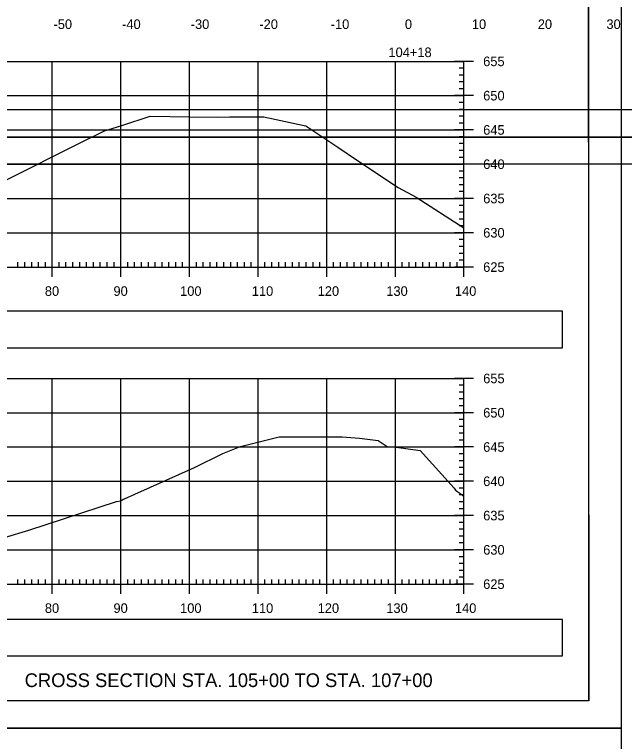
# Model space of a CAD drawing. Extents: x 1381471 to 1382703, y 370300 to 371487.
# Drawn here: x 1382079.3 to 1382168.2, y 370972.4 to 371078.4 of the extents above; entities that cross this region are included whole.
import ezdxf

# ---------------------------------------------------------------- set-up
doc = ezdxf.new("R2010")
doc.units = 0
for name, color, linetype in [('Level 15', 7, 'Continuous'), ('Level 18', 7, 'Continuous'), ('Level 22', 7, 'Continuous'), ('Level 26', 7, 'Continuous'), ('Level 4', 7, 'Continuous'), ('Level 45', 7, 'Continuous'), ('Level 5', 7, 'Continuous'), ('Level 6', 7, 'Continuous')]:
    doc.layers.add(name, color=color, linetype=linetype)

msp = doc.modelspace()

# ---------------------------------------------------------------- linework, layer by layer
at = {"layer": 'Level 18'}
for points in [[(1382078.02, 371054.19), (1382088.62, 371059.56), (1382092.36, 371061.41), (1382094.91, 371062.2), (1382099.03, 371063.56), (1382104.81, 371063.46), (1382108.85, 371063.42), (1382110.67, 371063.45), (1382115.58, 371063.45), (1382120.55, 371062.4), (1382121.71, 371062.14), (1382126.39, 371059.03), (1382129.23, 371057.09), (1382135.18, 371053.13), (1382137.81, 371051.74), (1382144.77, 371047.25)], [(1382077.82, 371002.09), (1382081.37, 371003.19), (1382094.14, 371007.36), (1382094.77, 371007.46), (1382095.09, 371007.68), (1382095.3, 371007.72), (1382096.81, 371008.41), (1382105.51, 371012.33), (1382109.63, 371014.35), (1382112.04, 371015.3), (1382112.15, 371015.34), (1382112.22, 371015.36), (1382117.82, 371016.76), (1382124.52, 371016.79), (1382127.01, 371016.79), (1382129.55, 371016.57), (1382132.27, 371016.23), (1382133.6, 371015.39), (1382134.89, 371015.28), (1382138.39, 371014.79), (1382143.35, 371009.28), (1382143.54, 371009.02), (1382143.7, 371008.93), (1382144.77, 371008.15)]]:
    msp.add_lwpolyline(points, dxfattribs=at)
at = {"layer": 'Level 22'}
for p, q in [((1381864.77, 371071.54), (1382144.77, 371071.54)), ((1382084.77, 371041.54), (1382084.77, 371071.54)), ((1382094.77, 371041.54), (1382094.77, 371071.54)), ((1382104.77, 371041.54), (1382104.77, 371071.54)), ((1382114.77, 371041.54), (1382114.77, 371071.54)), ((1382124.77, 371041.54), (1382124.77, 371071.54)), ((1382134.77, 371041.54), (1382134.77, 371071.54)), ((1382144.77, 371041.54), (1382144.77, 371071.54)), ((1381864.77, 371066.54), (1382144.77, 371066.54)), ((1381864.77, 371061.54), (1382144.77, 371061.54)), ((1381864.77, 371056.54), (1382144.77, 371056.54)), ((1381864.77, 371051.54), (1382144.77, 371051.54)), ((1381864.77, 371046.54), (1382144.77, 371046.54)), ((1381864.77, 371041.54), (1382144.77, 371041.54)), ((1381864.77, 371025.3), (1382144.77, 371025.3)), ((1382084.77, 370995.3), (1382084.77, 371025.3)), ((1382094.77, 370995.3), (1382094.77, 371025.3)), ((1382104.77, 370995.3), (1382104.77, 371025.3)), ((1382114.77, 370995.3), (1382114.77, 371025.3)), ((1382124.77, 370995.3), (1382124.77, 371025.3)), ((1382134.77, 370995.3), (1382134.77, 371025.3)), ((1382144.77, 370995.3), (1382144.77, 371025.3)), ((1381864.77, 371020.3), (1382144.77, 371020.3)), ((1381864.77, 371015.3), (1382144.77, 371015.3)), ((1381864.77, 371010.3), (1382144.77, 371010.3)), ((1381864.77, 371005.3), (1382144.77, 371005.3)), ((1381864.77, 371000.3), (1382144.77, 371000.3)), ((1381864.77, 370995.3), (1382144.77, 370995.3))]:
    msp.add_line(p, q, dxfattribs=at)
at = {"layer": 'Level 26'}
for p, q in [((1381834.37, 370974.31), (1382167.7, 370974.31)), ((1381834.37, 370974.3), (1382167.7, 370974.3))]:
    msp.add_line(p, q, dxfattribs=at)
for points in [[(1381834.36, 371187.64), (1382167.7, 371187.64), (1382167.7, 370974.3), (1381834.36, 370974.3)], [(1382080.69, 371183.75), (1382100.31, 371183.75), (1382100.31, 371173.87), (1382116.42, 371173.87), (1382139.62, 371173.87), (1382139.62, 371141.2), (1382162.83, 371141.2), (1382162.95, 370978.29), (1381846.77, 370978.29), (1381846.77, 371183.75)], [(1381834.36, 370974.3), (1382167.7, 370974.3), (1382167.7, 370760.97), (1381834.36, 370760.97)]]:
    msp.add_lwpolyline(points, close=True, dxfattribs=at)
at = {"layer": 'Level 4'}
for p, q in [((1382146.17, 371071.54), (1382143.37, 371071.54)), ((1382144.77, 371041.54), (1382144.77, 371071.54)), ((1382144.77, 371070.54), (1382144.07, 371070.54)), ((1382144.77, 371069.54), (1382144.07, 371069.54)), ((1382144.77, 371068.54), (1382144.07, 371068.54)), ((1382144.77, 371067.54), (1382144.07, 371067.54)), ((1382146.17, 371066.54), (1382143.37, 371066.54)), ((1382144.77, 371065.54), (1382144.07, 371065.54)), ((1382144.77, 371064.54), (1382144.07, 371064.54)), ((1382144.77, 371063.54), (1382144.07, 371063.54)), ((1382144.77, 371062.54), (1382144.07, 371062.54)), ((1382146.17, 371061.54), (1382143.37, 371061.54)), ((1382144.77, 371060.54), (1382144.07, 371060.54)), ((1382144.77, 371059.54), (1382144.07, 371059.54)), ((1382144.77, 371058.54), (1382144.07, 371058.54)), ((1382146.17, 371056.54), (1382143.37, 371056.54)), ((1382144.77, 371057.54), (1382144.07, 371057.54)), ((1382144.77, 371055.54), (1382144.07, 371055.54)), ((1382144.77, 371054.54), (1382144.07, 371054.54)), ((1382144.77, 371053.54), (1382144.07, 371053.54)), ((1382144.77, 371052.54), (1382144.07, 371052.54)), ((1382146.17, 371051.54), (1382143.37, 371051.54)), ((1382144.77, 371050.54), (1382144.07, 371050.54)), ((1382144.77, 371049.54), (1382144.07, 371049.54)), ((1382144.77, 371048.54), (1382144.07, 371048.54)), ((1382144.77, 371047.54), (1382144.07, 371047.54)), ((1382146.17, 371046.54), (1382143.37, 371046.54)), ((1382144.77, 371045.54), (1382144.07, 371045.54)), ((1382144.77, 371044.54), (1382144.07, 371044.54)), ((1382084.77, 371040.14), (1382084.77, 371042.94)), ((1382094.77, 371040.14), (1382094.77, 371042.94)), ((1382104.77, 371040.14), (1382104.77, 371042.94)), ((1382114.77, 371040.14), (1382114.77, 371042.94)), ((1382124.77, 371040.14), (1382124.77, 371042.94)), ((1382134.77, 371040.14), (1382134.77, 371042.94)), ((1382144.77, 371043.54), (1382144.07, 371043.54)), ((1382144.77, 371040.14), (1382144.77, 371042.94)), ((1382079.77, 371041.54), (1382079.77, 371042.24)), ((1382080.77, 371041.54), (1382080.77, 371042.24)), ((1382081.77, 371041.54), (1382081.77, 371042.24)), ((1382082.77, 371041.54), (1382082.77, 371042.24)), ((1382083.77, 371041.54), (1382083.77, 371042.24)), ((1382085.77, 371041.54), (1382085.77, 371042.24)), ((1382086.77, 371041.54), (1382086.77, 371042.24)), ((1382087.77, 371041.54), (1382087.77, 371042.24)), ((1382088.77, 371041.54), (1382088.77, 371042.24)), ((1382089.77, 371041.54), (1382089.77, 371042.24)), ((1382090.77, 371041.54), (1382090.77, 371042.24)), ((1382091.77, 371041.54), (1382091.77, 371042.24)), ((1382092.77, 371041.54), (1382092.77, 371042.24)), ((1382093.77, 371041.54), (1382093.77, 371042.24)), ((1382095.77, 371041.54), (1382095.77, 371042.24)), ((1382096.77, 371041.54), (1382096.77, 371042.24)), ((1382097.77, 371041.54), (1382097.77, 371042.24)), ((1382098.77, 371041.54), (1382098.77, 371042.24)), ((1382099.77, 371041.54), (1382099.77, 371042.24)), ((1382100.77, 371041.54), (1382100.77, 371042.24)), ((1382101.77, 371041.54), (1382101.77, 371042.24)), ((1382102.77, 371041.54), (1382102.77, 371042.24)), ((1382103.77, 371041.54), (1382103.77, 371042.24)), ((1382105.77, 371041.54), (1382105.77, 371042.24)), ((1382106.77, 371041.54), (1382106.77, 371042.24)), ((1382107.77, 371041.54), (1382107.77, 371042.24)), ((1382108.77, 371041.54), (1382108.77, 371042.24)), ((1382109.77, 371041.54), (1382109.77, 371042.24)), ((1382110.77, 371041.54), (1382110.77, 371042.24)), ((1382111.77, 371041.54), (1382111.77, 371042.24)), ((1382112.77, 371041.54), (1382112.77, 371042.24)), ((1382113.77, 371041.54), (1382113.77, 371042.24)), ((1382115.77, 371041.54), (1382115.77, 371042.24)), ((1382116.77, 371041.54), (1382116.77, 371042.24)), ((1382117.77, 371041.54), (1382117.77, 371042.24)), ((1382118.77, 371041.54), (1382118.77, 371042.24)), ((1382119.77, 371041.54), (1382119.77, 371042.24)), ((1382120.77, 371041.54), (1382120.77, 371042.24)), ((1382121.77, 371041.54), (1382121.77, 371042.24)), ((1382122.77, 371041.54), (1382122.77, 371042.24)), ((1382123.77, 371041.54), (1382123.77, 371042.24)), ((1382125.77, 371041.54), (1382125.77, 371042.24)), ((1382126.77, 371041.54), (1382126.77, 371042.24)), ((1382127.77, 371041.54), (1382127.77, 371042.24)), ((1382128.77, 371041.54), (1382128.77, 371042.24)), ((1382129.77, 371041.54), (1382129.77, 371042.24)), ((1382130.77, 371041.54), (1382130.77, 371042.24)), ((1382131.77, 371041.54), (1382131.77, 371042.24)), ((1382132.77, 371041.54), (1382132.77, 371042.24)), ((1382133.77, 371041.54), (1382133.77, 371042.24)), ((1382135.77, 371041.54), (1382135.77, 371042.24)), ((1382136.77, 371041.54), (1382136.77, 371042.24)), ((1382137.77, 371041.54), (1382137.77, 371042.24)), ((1382138.77, 371041.54), (1382138.77, 371042.24)), ((1382139.77, 371041.54), (1382139.77, 371042.24)), ((1382140.77, 371041.54), (1382140.77, 371042.24)), ((1382141.77, 371041.54), (1382141.77, 371042.24)), ((1382142.77, 371041.54), (1382142.77, 371042.24)), ((1382143.77, 371041.54), (1382143.77, 371042.24)), ((1382144.77, 371042.54), (1382144.07, 371042.54)), ((1381864.77, 371041.54), (1382144.77, 371041.54)), ((1382146.17, 371041.54), (1382143.37, 371041.54)), ((1382146.17, 371025.3), (1382143.37, 371025.3)), ((1382144.77, 370995.3), (1382144.77, 371025.3)), ((1382144.77, 371024.3), (1382144.07, 371024.3)), ((1382144.77, 371023.3), (1382144.07, 371023.3)), ((1382144.77, 371022.3), (1382144.07, 371022.3)), ((1382144.77, 371021.3), (1382144.07, 371021.3)), ((1382146.17, 371020.3), (1382143.37, 371020.3)), ((1382144.77, 371019.3), (1382144.07, 371019.3)), ((1382144.77, 371018.3), (1382144.07, 371018.3)), ((1382144.77, 371017.3), (1382144.07, 371017.3)), ((1382144.77, 371016.3), (1382144.07, 371016.3)), ((1382146.17, 371015.3), (1382143.37, 371015.3)), ((1382144.77, 371014.3), (1382144.07, 371014.3)), ((1382144.77, 371013.3), (1382144.07, 371013.3)), ((1382144.77, 371012.3), (1382144.07, 371012.3)), ((1382144.77, 371011.3), (1382144.07, 371011.3)), ((1382146.17, 371010.3), (1382143.37, 371010.3)), ((1382144.77, 371009.3), (1382144.07, 371009.3)), ((1382144.77, 371008.3), (1382144.07, 371008.3)), ((1382144.77, 371007.3), (1382144.07, 371007.3)), ((1382144.77, 371006.3), (1382144.07, 371006.3)), ((1382146.17, 371005.3), (1382143.37, 371005.3)), ((1382144.77, 371004.3), (1382144.07, 371004.3)), ((1382144.77, 371003.3), (1382144.07, 371003.3)), ((1382144.77, 371002.3), (1382144.07, 371002.3)), ((1382144.77, 371001.3), (1382144.07, 371001.3)), ((1382146.17, 371000.3), (1382143.37, 371000.3)), ((1382144.77, 370999.3), (1382144.07, 370999.3)), ((1382144.77, 370998.3), (1382144.07, 370998.3)), ((1382144.77, 370997.3), (1382144.07, 370997.3)), ((1382084.77, 370993.9), (1382084.77, 370996.7)), ((1382094.77, 370993.9), (1382094.77, 370996.7)), ((1382104.77, 370993.9), (1382104.77, 370996.7)), ((1382114.77, 370993.9), (1382114.77, 370996.7)), ((1382124.77, 370993.9), (1382124.77, 370996.7)), ((1382134.77, 370993.9), (1382134.77, 370996.7)), ((1382144.77, 370996.3), (1382144.07, 370996.3)), ((1382144.77, 370993.9), (1382144.77, 370996.7)), ((1381864.77, 370995.3), (1382144.77, 370995.3)), ((1382079.77, 370995.3), (1382079.77, 370996)), ((1382080.77, 370995.3), (1382080.77, 370996)), ((1382081.77, 370995.3), (1382081.77, 370996)), ((1382082.77, 370995.3), (1382082.77, 370996)), ((1382083.77, 370995.3), (1382083.77, 370996)), ((1382085.77, 370995.3), (1382085.77, 370996)), ((1382086.77, 370995.3), (1382086.77, 370996)), ((1382087.77, 370995.3), (1382087.77, 370996)), ((1382088.77, 370995.3), (1382088.77, 370996)), ((1382089.77, 370995.3), (1382089.77, 370996)), ((1382090.77, 370995.3), (1382090.77, 370996)), ((1382091.77, 370995.3), (1382091.77, 370996)), ((1382092.77, 370995.3), (1382092.77, 370996)), ((1382093.77, 370995.3), (1382093.77, 370996)), ((1382095.77, 370995.3), (1382095.77, 370996)), ((1382096.77, 370995.3), (1382096.77, 370996)), ((1382097.77, 370995.3), (1382097.77, 370996)), ((1382098.77, 370995.3), (1382098.77, 370996)), ((1382099.77, 370995.3), (1382099.77, 370996)), ((1382100.77, 370995.3), (1382100.77, 370996)), ((1382101.77, 370995.3), (1382101.77, 370996)), ((1382102.77, 370995.3), (1382102.77, 370996)), ((1382103.77, 370995.3), (1382103.77, 370996)), ((1382105.77, 370995.3), (1382105.77, 370996)), ((1382106.77, 370995.3), (1382106.77, 370996)), ((1382107.77, 370995.3), (1382107.77, 370996)), ((1382108.77, 370995.3), (1382108.77, 370996)), ((1382109.77, 370995.3), (1382109.77, 370996)), ((1382110.77, 370995.3), (1382110.77, 370996)), ((1382111.77, 370995.3), (1382111.77, 370996)), ((1382112.77, 370995.3), (1382112.77, 370996)), ((1382113.77, 370995.3), (1382113.77, 370996)), ((1382115.77, 370995.3), (1382115.77, 370996)), ((1382116.77, 370995.3), (1382116.77, 370996)), ((1382117.77, 370995.3), (1382117.77, 370996)), ((1382118.77, 370995.3), (1382118.77, 370996)), ((1382119.77, 370995.3), (1382119.77, 370996)), ((1382120.77, 370995.3), (1382120.77, 370996)), ((1382121.77, 370995.3), (1382121.77, 370996)), ((1382122.77, 370995.3), (1382122.77, 370996)), ((1382123.77, 370995.3), (1382123.77, 370996)), ((1382125.77, 370995.3), (1382125.77, 370996)), ((1382126.77, 370995.3), (1382126.77, 370996)), ((1382127.77, 370995.3), (1382127.77, 370996)), ((1382128.77, 370995.3), (1382128.77, 370996)), ((1382129.77, 370995.3), (1382129.77, 370996)), ((1382130.77, 370995.3), (1382130.77, 370996)), ((1382131.77, 370995.3), (1382131.77, 370996)), ((1382132.77, 370995.3), (1382132.77, 370996)), ((1382133.77, 370995.3), (1382133.77, 370996)), ((1382135.77, 370995.3), (1382135.77, 370996)), ((1382136.77, 370995.3), (1382136.77, 370996)), ((1382137.77, 370995.3), (1382137.77, 370996)), ((1382138.77, 370995.3), (1382138.77, 370996)), ((1382139.77, 370995.3), (1382139.77, 370996)), ((1382140.77, 370995.3), (1382140.77, 370996)), ((1382141.77, 370995.3), (1382141.77, 370996)), ((1382142.77, 370995.3), (1382142.77, 370996)), ((1382146.17, 370995.3), (1382143.37, 370995.3)), ((1382143.77, 370995.3), (1382143.77, 370996))]:
    msp.add_line(p, q, dxfattribs=at)
at = {"layer": 'Level 45'}
for p, q in [((1382294.79, 371064.46), (1381978.61, 371064.46)), ((1381966.21, 371060.48), (1382299.55, 371060.48)), ((1381966.21, 371060.47), (1382299.55, 371060.47)), ((1381978.61, 371056.58), (1382294.79, 371056.58)), ((1382131.13, 371056.32), (1382131.13, 371056.32)), ((1382131.13, 371056.32), (1382131.13, 371056.32))]:
    msp.add_line(p, q, dxfattribs=at)
for points in [[(1381966.21, 371273.81), (1382299.55, 371273.81), (1382299.55, 371060.48), (1381966.21, 371060.48)], [(1382212.53, 371269.92), (1382232.15, 371269.92), (1382232.15, 371260.04), (1382248.27, 371260.04), (1382271.46, 371260.04), (1382271.46, 371235.71), (1382294.79, 371235.71), (1382294.79, 371064.46), (1381978.61, 371064.46), (1381978.61, 371269.92)], [(1381966.21, 371060.47), (1382299.55, 371060.47), (1382299.55, 370847.14), (1381966.21, 370847.14)], [(1382212.53, 371056.58), (1382232.15, 371056.58), (1382232.15, 371046.7), (1382248.27, 371046.7), (1382271.46, 371046.7), (1382271.46, 371022.37), (1382294.79, 371022.37), (1382294.79, 370851.12), (1381978.61, 370851.12), (1381978.61, 371056.58)]]:
    msp.add_lwpolyline(points, close=True, dxfattribs=at)
at = {"layer": 'Level 6'}
for q in [(1382162.95, 371183.75), (1381846.77, 370978.29)]:
    msp.add_line((1382162.95, 370978.29), q, dxfattribs=at)
for points in [[(1381850.41, 371029.76), (1382159.14, 371029.76), (1382159.14, 371035.09), (1381850.41, 371035.09)], [(1381850.41, 370984.82), (1382159.14, 370984.82), (1382159.14, 370990.14), (1381850.41, 370990.14)]]:
    msp.add_lwpolyline(points, close=True, dxfattribs=at)

# ---------------------------------------------------------------- texts
at = {"layer": 'Level 15'}
msp.add_text('CROSS SECTION STA. 105+00 TO STA. 107+00', height=2, dxfattribs=at).set_placement((1382080.75, 370980.29))
at = {"layer": 'Level 45'}
for s, p in [('-50', (1382084.95, 371076.26)), ('-40', (1382094.95, 371076.26)), ('-30', (1382104.95, 371076.26)), ('-20', (1382114.95, 371076.26)), ('-10', (1382125.35, 371076.26)), ('0', (1382136.16, 371076.26)), ('10', (1382145.92, 371076.26)), ('20', (1382155.53, 371076.26)), ('30', (1382165.53, 371076.26)), ('104+18', (1382133.76, 371072.16))]:
    msp.add_text(s, height=1.4, dxfattribs=at).set_placement(p)
at = {"layer": 'Level 5'}
for s, p in [('655', (1382147.57, 371070.84)), ('650', (1382147.57, 371065.84)), ('645', (1382147.57, 371060.84)), ('640', (1382147.57, 371055.84)), ('635', (1382147.57, 371050.84)), ('630', (1382147.57, 371045.84)), ('625', (1382147.57, 371040.84)), ('80', (1382083.69, 371037.34)), ('90', (1382093.69, 371037.34)), ('100', (1382103.4, 371037.34)), ('110', (1382113.85, 371037.34)), ('120', (1382123.45, 371037.34)), ('130', (1382133.45, 371037.34)), ('140', (1382143.45, 371037.34)), ('655', (1382147.57, 371024.6)), ('650', (1382147.57, 371019.6)), ('645', (1382147.57, 371014.6)), ('640', (1382147.57, 371009.6)), ('635', (1382147.57, 371004.6)), ('630', (1382147.57, 370999.6)), ('625', (1382147.57, 370994.6)), ('80', (1382083.69, 370991.1)), ('90', (1382093.69, 370991.1)), ('100', (1382103.4, 370991.1)), ('110', (1382113.85, 370991.1)), ('120', (1382123.45, 370991.1)), ('130', (1382133.45, 370991.1)), ('140', (1382143.45, 370991.1))]:
    msp.add_text(s, height=1.4, dxfattribs=at).set_placement(p)

doc.saveas('drawing.dxf')
